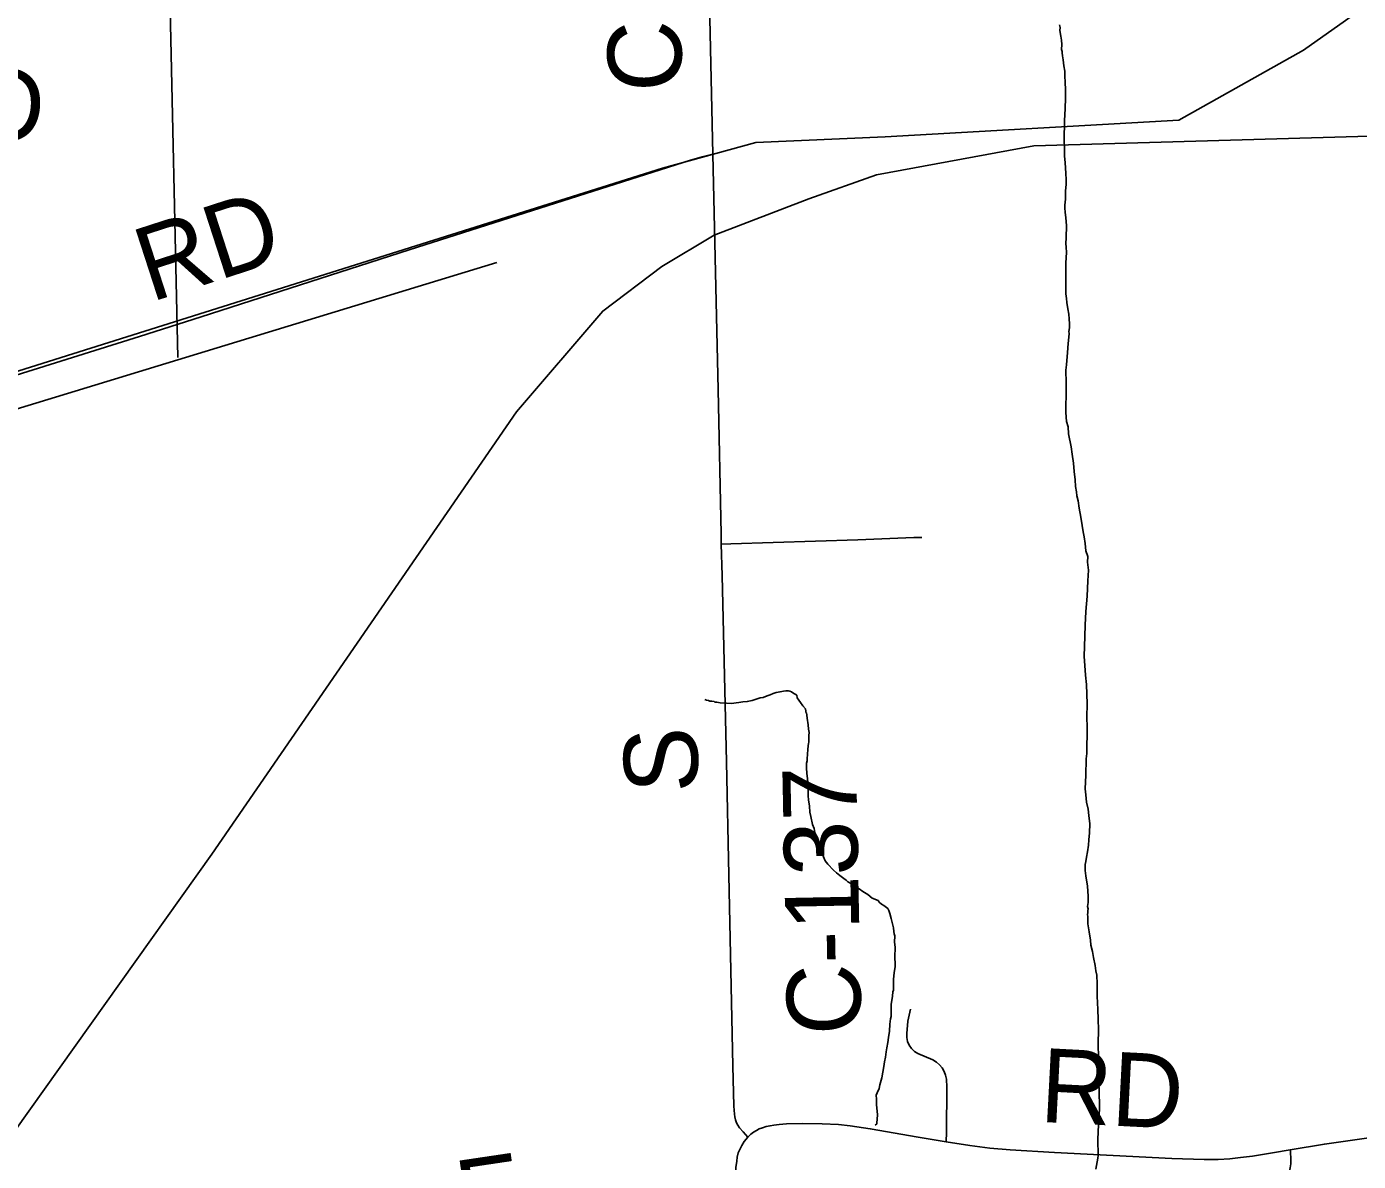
# Model space of a CAD drawing. Extents: x 63.4 to 97.4, y 0.4 to 22.4.
# Drawn here: x 69.704 to 70.728, y 15.976 to 16.848 of the extents above; entities that cross this region are included whole.
import ezdxf

# ---------------------------------------------------------------- set-up
doc = ezdxf.new("R2010")
doc.units = 0
for name, color, linetype in [('GM_X_County_Road', 7, 'Continuous'), ('GM_X_County_Road_Text', 7, 'Continuous'), ('GM_X_Minor_River', 7, 'Continuous'), ('GM_X_Rail_Line', 7, 'Continuous'), ('GM_X_Township_Road', 7, 'Continuous'), ('GM_X_Township_Road_Text', 7, 'Continuous')]:
    doc.layers.add(name, color=color, linetype=linetype)

msp = doc.modelspace()

# ---------------------------------------------------------------- linework, layer by layer
at = {"layer": 'GM_X_County_Road'}
for points in [[(70.2316, 16.7501), (70.2293, 16.8544), (70.2287, 16.8754)], [(69.6745, 16.5737), (69.7908, 16.61), (69.8382, 16.625), (69.9981, 16.6766), (70.1107, 16.7126), (70.2145, 16.7455), (70.2235, 16.748), (70.2316, 16.7501)], [(70.2381, 16.4503), (70.238, 16.458), (70.2358, 16.5693), (70.2343, 16.6255), (70.2316, 16.7501)], [(70.2585, 15.9947), (70.2548, 15.9986), (70.2521, 16.0018), (70.2508, 16.0038), (70.2499, 16.0056), (70.249, 16.0078), (70.2484, 16.0101), (70.2482, 16.0123), (70.2477, 16.0185), (70.2471, 16.0495), (70.244, 16.1959), (70.2421, 16.2831), (70.2387, 16.4264), (70.2381, 16.4503)], [(70.2585, 15.9947), (70.2607, 15.9968), (70.2629, 15.9985), (70.2651, 15.9998), (70.2673, 16.0009), (70.2698, 16.0018), (70.2726, 16.0027), (70.2756, 16.0034), (70.2786, 16.0039), (70.2826, 16.0043), (70.2883, 16.0047), (70.3002, 16.0051), (70.3157, 16.0049), (70.3281, 16.0043), (70.3373, 16.0034), (70.3527, 16.0011), (70.3894, 15.9947), (70.4111, 15.9911)], [(70.2361, 15.9004), (70.237, 15.9009), (70.2396, 15.9023), (70.2417, 15.904), (70.2439, 15.906), (70.2458, 15.9083), (70.2474, 15.9108), (70.2485, 15.9135), (70.2498, 15.9194), (70.2501, 15.9286), (70.2493, 15.966), (70.2494, 15.9712), (70.25, 15.9762), (70.2504, 15.9792), (70.2512, 15.9825), (70.2525, 15.9857), (70.2538, 15.9883), (70.2558, 15.9913), (70.2585, 15.9947)], [(70.6756, 15.9848), (70.7018, 15.9892), (70.7682, 15.9987)], [(70.4111, 15.9911), (70.4293, 15.9881), (70.4447, 15.9861), (70.4602, 15.9848), (70.4944, 15.9828), (70.5844, 15.9781), (70.6093, 15.9775), (70.6202, 15.9775), (70.629, 15.9779), (70.6372, 15.9789), (70.6466, 15.9801), (70.6619, 15.9825), (70.6756, 15.9848)]]:
    msp.add_lwpolyline(points, dxfattribs=at)
at = {"layer": 'GM_X_Minor_River'}
for points in [[(69.8556, 17.1284), (69.8602, 16.8901), (69.8139, 16.8853), (69.8203, 16.5938)], [(70.5078, 16.5195), (70.5071, 16.5252), (70.505, 16.5351), (70.5047, 16.5405), (70.5036, 16.5447), (70.5033, 16.5481), (70.5029, 16.5519), (70.5032, 16.5697), (70.5032, 16.572), (70.5033, 16.5769), (70.503, 16.5815), (70.503, 16.5842), (70.5035, 16.5883), (70.5044, 16.5978), (70.5049, 16.6046), (70.5053, 16.6096), (70.5057, 16.6122), (70.5054, 16.6138), (70.5058, 16.6168), (70.5058, 16.6198), (70.5055, 16.6236), (70.5052, 16.6271), (70.5045, 16.6312), (70.5038, 16.6362), (70.5035, 16.6392), (70.5031, 16.6427), (70.503, 16.6563), (70.5031, 16.6666), (70.5036, 16.6745), (70.5033, 16.6787), (70.503, 16.6814), (70.5034, 16.6859), (70.5035, 16.6954), (70.5029, 16.7011), (70.5026, 16.7057), (70.5022, 16.7087), (70.5023, 16.711), (70.5027, 16.7156), (70.5028, 16.7217), (70.5032, 16.727), (70.5033, 16.7308), (70.503, 16.7353), (70.5024, 16.7437), (70.502, 16.7486), (70.5021, 16.7547), (70.5018, 16.7608), (70.5021, 16.776), (70.5026, 16.7851), (70.5027, 16.7934), (70.5028, 16.8018), (70.5025, 16.8033), (70.5025, 16.8063), (70.5022, 16.8094), (70.5023, 16.8139), (70.5016, 16.8181), (70.5009, 16.8227), (70.5005, 16.8257), (70.5002, 16.828), (70.5002, 16.8292), (70.4998, 16.8307), (70.4999, 16.8345), (70.4996, 16.8379), (70.4992, 16.8409), (70.4985, 16.8451), (70.4986, 16.8474), (70.4982, 16.8497)], [(70.0656, 16.6668), (69.0959, 16.3711), (69.1045, 16.1112), (69.0411, 16.1078), (69.0357, 16.1196), (68.9864, 16.1186), (68.9377, 16.1412)], [(70.5262, 15.9701), (70.5275, 15.9785), (70.5279, 15.9804), (70.5279, 15.9815), (70.5277, 15.9918), (70.5278, 15.9997), (70.5287, 16.0092), (70.5288, 16.0191), (70.5286, 16.0286), (70.5284, 16.0373), (70.5281, 16.0457), (70.5282, 16.0552), (70.528, 16.0666), (70.5282, 16.0772), (70.5279, 16.0852), (70.5276, 16.0928), (70.527, 16.103), (70.5272, 16.1125), (70.5269, 16.119), (70.5262, 16.1224), (70.5255, 16.1266), (70.5244, 16.1327), (70.5234, 16.1373), (70.5223, 16.1422), (70.522, 16.146), (70.5209, 16.1525), (70.5199, 16.1586), (70.52, 16.1643), (70.5196, 16.1658), (70.52, 16.1669), (70.52, 16.1688), (70.5201, 16.17), (70.5197, 16.1719), (70.5201, 16.1749), (70.5202, 16.1798), (70.5196, 16.1874), (70.5185, 16.1954), (70.5178, 16.1996), (70.5179, 16.2042), (70.5183, 16.2065), (70.5188, 16.2099), (70.5196, 16.214), (70.5204, 16.219), (70.5208, 16.2231), (70.5213, 16.2284), (70.5214, 16.2353), (70.5207, 16.2417), (70.5201, 16.2467), (70.519, 16.252), (70.5183, 16.2577), (70.518, 16.2623), (70.5181, 16.2676), (70.5185, 16.2725), (70.5187, 16.2854), (70.5192, 16.2896), (70.5195, 16.3097), (70.5192, 16.3173), (70.5194, 16.3276), (70.5191, 16.3352), (70.5188, 16.3424), (70.5182, 16.3496), (70.5175, 16.3572), (70.5172, 16.3641), (70.5175, 16.3796), (70.518, 16.388), (70.5185, 16.3986), (70.5194, 16.4104), (70.52, 16.4221), (70.5205, 16.4305), (70.5198, 16.4366), (70.5199, 16.4408), (70.5184, 16.4453), (70.5178, 16.451), (70.5171, 16.456), (70.5164, 16.4598), (70.5157, 16.4647), (70.5146, 16.4712), (70.5132, 16.4781), (70.5126, 16.4838), (70.5115, 16.4876), (70.5111, 16.4906), (70.5104, 16.4948), (70.5101, 16.4998), (70.5095, 16.5062), (70.5088, 16.5127), (70.5078, 16.5195)], [(70.3031, 16.3219), (70.3028, 16.3238), (70.3009, 16.3261), (70.2991, 16.3288), (70.2965, 16.3323), (70.2961, 16.3342), (70.2931, 16.3361), (70.292, 16.3369), (70.2909, 16.3373), (70.2897, 16.3377), (70.2878, 16.3377), (70.2859, 16.3373), (70.2833, 16.337), (70.2802, 16.3363), (70.2779, 16.3356), (70.2756, 16.3345), (70.2734, 16.3337), (70.2703, 16.3326), (70.268, 16.3323), (70.2619, 16.3301), (70.2581, 16.3294), (70.2547, 16.3291), (70.2517, 16.3287), (70.2456, 16.328), (70.2422, 16.3281), (70.2373, 16.3285), (70.2346, 16.329), (70.2331, 16.329), (70.2327, 16.3294), (70.2308, 16.3298), (70.2293, 16.3298), (70.2282, 16.3302), (70.2267, 16.3306), (70.2255, 16.331)], [(70.3565, 16.0037), (70.3576, 16.0048), (70.3576, 16.0059), (70.358, 16.0082), (70.3581, 16.012), (70.3578, 16.0169), (70.3575, 16.0196), (70.3575, 16.0238), (70.3572, 16.0268), (70.358, 16.0287), (70.3595, 16.0321), (70.36, 16.0348), (70.3616, 16.0401), (70.3624, 16.0446), (70.3632, 16.0488), (70.3636, 16.0526), (70.3644, 16.056), (70.3649, 16.0601), (70.3653, 16.0632), (70.3661, 16.0673), (70.3666, 16.0711), (70.3674, 16.076), (70.3678, 16.0814), (70.3683, 16.0855), (70.3687, 16.0874), (70.3688, 16.0969), (70.3693, 16.0996), (70.3697, 16.103), (70.3701, 16.1064), (70.3705, 16.1075), (70.3706, 16.1159), (70.3711, 16.1208), (70.3715, 16.1242), (70.3719, 16.1254), (70.3719, 16.1276), (70.3716, 16.133), (70.3718, 16.1406), (70.3714, 16.1444), (70.3715, 16.1493), (70.3711, 16.1508), (70.3708, 16.1527), (70.3705, 16.1554), (70.3694, 16.1596), (70.3687, 16.1626), (70.3676, 16.1664), (70.3669, 16.1687), (70.3661, 16.1703), (70.3631, 16.1726), (70.3612, 16.1737), (70.3594, 16.1753), (70.3586, 16.1764), (70.3541, 16.1784), (70.3507, 16.1811), (70.347, 16.1834), (70.344, 16.1854), (70.3421, 16.1865), (70.3406, 16.1877), (70.3387, 16.1889), (70.3365, 16.1904), (70.3353, 16.1908), (70.3342, 16.192), (70.3323, 16.1935), (70.3293, 16.1958), (70.3267, 16.1978), (70.3245, 16.1997), (70.32, 16.2043), (70.3181, 16.207), (70.3167, 16.2101), (70.3145, 16.2162), (70.3127, 16.2223), (70.3116, 16.2257), (70.3101, 16.2288), (70.3094, 16.2318), (70.3083, 16.2349), (70.3069, 16.241), (70.3062, 16.2444), (70.3059, 16.249), (70.3052, 16.2539), (70.3048, 16.2569), (70.3049, 16.26), (70.3046, 16.2642), (70.3046, 16.2672), (70.3043, 16.2699), (70.304, 16.2744), (70.3036, 16.2782), (70.3037, 16.282), (70.3041, 16.2839), (70.3041, 16.2854), (70.3046, 16.2926), (70.305, 16.2953), (70.3051, 16.2972), (70.3054, 16.2983), (70.3055, 16.3033), (70.3056, 16.3055), (70.3052, 16.3082), (70.3049, 16.3116), (70.3042, 16.3166), (70.3039, 16.3189), (70.3035, 16.3208), (70.3031, 16.3212), (70.3031, 16.3219)]]:
    msp.add_lwpolyline(points, dxfattribs=at)
at = {"layer": 'GM_X_Rail_Line'}
for points in [[(65.5072, 16.0914), (66.1191, 16.083), (66.4239, 16.0787), (66.8313, 16.0688), (67.543, 16.0626), (67.9702, 16.0577), (68.6101, 16.2463), (69.1053, 16.3972), (70.1929, 16.7393), (70.2646, 16.7591), (70.3642, 16.7634), (70.5898, 16.7764), (70.6857, 16.8302), (70.7827, 16.8988), (71.2174, 17.2501), (71.5086, 17.4876), (71.6576, 17.6039), (72.13, 17.975), (72.3072, 18.116)], [(69.3319, 14.8787), (69.2942, 14.9743), (69.2629, 15.0308), (69.214, 15.1273), (69.2031, 15.1476), (69.1971, 15.1765), (69.195, 15.2169), (69.2031, 15.259), (69.2208, 15.2984), (69.2996, 15.424), (69.5191, 15.7529), (69.8464, 16.212), (70.0807, 16.5521), (70.1469, 16.6295), (70.1923, 16.6638), (70.2325, 16.6879), (70.3054, 16.7158), (70.3574, 16.7343), (70.4785, 16.7566), (71.288, 16.7798)]]:
    msp.add_lwpolyline(points, dxfattribs=at)
at = {"layer": 'GM_X_Township_Road'}
for points in [[(70.2381, 16.4503), (70.2454, 16.4506), (70.343, 16.4538), (70.3861, 16.4555), (70.3923, 16.4554)], [(70.4111, 15.9911), (70.4112, 15.9984), (70.4116, 16.0329), (70.4113, 16.0391), (70.4106, 16.0422), (70.4095, 16.0451), (70.4079, 16.0478), (70.4058, 16.0502), (70.4035, 16.0522), (70.4008, 16.0539), (70.3892, 16.0588), (70.3866, 16.0605), (70.3843, 16.0627), (70.3826, 16.0652), (70.3814, 16.0681), (70.3808, 16.0712), (70.3807, 16.0743), (70.3815, 16.0837), (70.3835, 16.0929)], [(70.6912, 15.9438), (70.6902, 15.9452), (70.6881, 15.9475), (70.6856, 15.9493), (70.6799, 15.9519), (70.6772, 15.9535), (70.6751, 15.9557), (70.674, 15.9585), (70.6738, 15.9616), (70.6742, 15.9647), (70.6755, 15.9709), (70.6759, 15.974), (70.6761, 15.9771), (70.6757, 15.9837), (70.6756, 15.9848)]]:
    msp.add_lwpolyline(points, dxfattribs=at)

# ---------------------------------------------------------------- texts
at = {"layer": 'GM_X_County_Road_Text'}
for s, height, rotation, p in [('CHURCH', 0.05682, 91.1467, (70.2081, 16.7986)), ('RD', 0.05682, 17.9697, (69.7994, 16.6362)), ('S', 0.0568, 91.283, (70.2206, 16.2597)), ('C-137', 0.05682, 91.1032, (70.3458, 16.0735)), ('RD', 0.05682, 357.0387, (70.4824, 16.0064)), ('E', 0.0568, 8.4625, (70.0391, 15.9195))]:
    msp.add_text(s, height=height, rotation=rotation, dxfattribs=at).set_placement(p)
at = {"layer": 'GM_X_Township_Road_Text'}
msp.add_text('D', height=0.0568, rotation=357.6972, dxfattribs=at).set_placement((69.662, 16.761))

doc.saveas('drawing.dxf')
